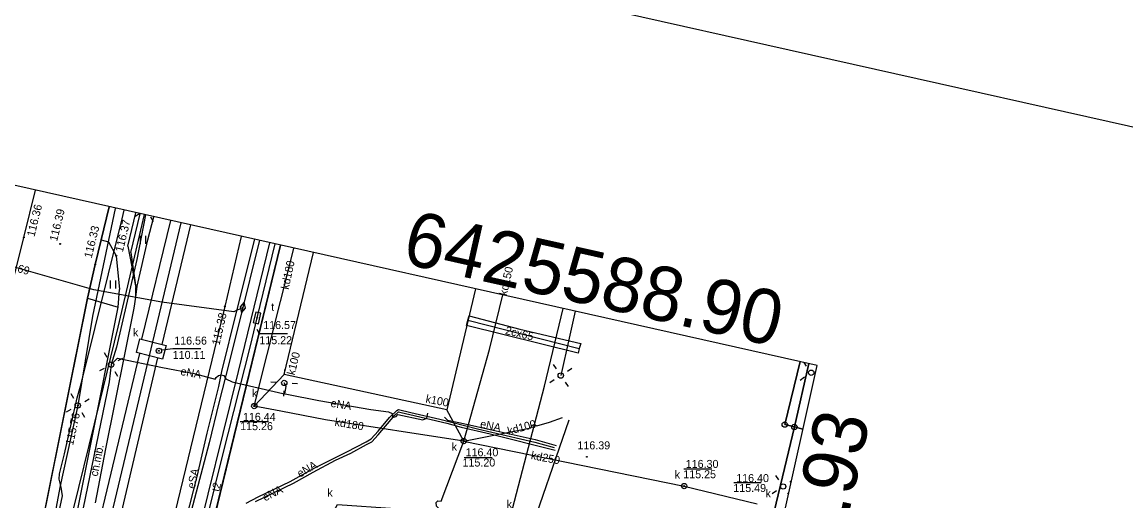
# Model space of a CAD drawing. Extents: x 6424617 to 6425697, y 5665845 to 5667190.
# Drawn here: x 6425514.4 to 6425617.8, y 5666988.2 to 5667033.1 of the extents above; entities that cross this region are included whole.
import ezdxf

# ---------------------------------------------------------------- set-up
doc = ezdxf.new("R2010")
doc.units = 0
for name, color, linetype in [('Warstwa 1', 7, 'Continuous'), ('Warstwa 10', 7, 'Continuous'), ('Warstwa 11', 7, 'Continuous'), ('Warstwa 12', 7, 'Continuous'), ('Warstwa 13', 7, 'Continuous'), ('Warstwa 14', 7, 'Continuous'), ('Warstwa 15', 7, 'Continuous'), ('Warstwa 16', 7, 'Continuous'), ('Warstwa 19', 7, 'Continuous'), ('Warstwa 2', 7, 'Continuous'), ('Warstwa 25', 7, 'Continuous'), ('Warstwa 4', 7, 'Continuous'), ('Warstwa 5', 7, 'Continuous'), ('Warstwa 6', 7, 'Continuous'), ('Warstwa 61', 7, 'Continuous'), ('Warstwa 63', 7, 'Continuous'), ('Warstwa 8', 7, 'Continuous'), ('Warstwa 9', 7, 'Continuous')]:
    doc.layers.add(name, color=color, linetype=linetype)

msp = doc.modelspace()

# ---------------------------------------------------------------- linework, layer by layer
at = {"layer": 'Warstwa 1'}
for p, q in [((6425527.3, 5666965.75), (6425538.59, 5667012.21)), ((6425527.3, 5666965.75), (6425538.59, 5667012.21)), ((6425585.85, 5666995.38), (6425587.28, 5667001.29)), ((6425585.85, 5666995.38), (6425587.28, 5667001.29)), ((6425578.8, 5666961.99), (6425586.75, 5666995.16)), ((6425578.8, 5666961.99), (6425586.75, 5666995.16)), ((6425585.85, 5666995.38), (6425586.75, 5666995.16)), ((6425585.85, 5666995.38), (6425586.75, 5666995.16)), ((6425586.75, 5666995.16), (6425587.56, 5666994.96)), ((6425586.75, 5666995.16), (6425587.56, 5666994.96))]:
    msp.add_line(p, q, dxfattribs=at)
msp.add_lwpolyline([(6425556.88, 5667008.11), (6425554.18, 5666996.75), (6425538.92, 5667000.09), (6425541.67, 5667011.52)], dxfattribs=at)
at = {"layer": 'Warstwa 10'}
for points in [[(6425536.15, 5667012.76), (6425534.48, 5667006.06), (6425533.07, 5667000.35), (6425532.79, 5666998.95), (6425531.7, 5666994.57), (6425530.74, 5666990.52), (6425529.72, 5666986.47), (6425527.95, 5666979.51), (6425526.81, 5666974.7), (6425525.74, 5666970.26), (6425525.2, 5666968.28), (6425524.22, 5666964.01), (6425522.97, 5666958.26), (6425521.24, 5666950.95), (6425520.79, 5666949.08), (6425520.74, 5666948.53), (6425520.56, 5666947.95), (6425520.42, 5666946.76), (6425520.15, 5666945.51), (6425519.52, 5666941.75), (6425519.08, 5666939.94), (6425519.11, 5666939.8), (6425519.37, 5666939.46)], [(6425536.61, 5667012.65), (6425536.33, 5667011.54), (6425535.06, 5667006.36)], [(6425535.06, 5667006.36), (6425534.21, 5667005.96), (6425527.47, 5667006.87), (6425521.11, 5667008.02), (6425511.65, 5667010.69), (6425511.04, 5667010.12), (6425510.23, 5667005.12), (6425507.8, 5666997.47), (6425502.22, 5666979.23), (6425499.7, 5666975.32), (6425496.98, 5666963.87), (6425497.18, 5666963.16), (6425549.77, 5666949.56), (6425554.77, 5666947.54), (6425572.63, 5666943.55), (6425574.23, 5666942.49)], [(6425535.06, 5667006.36), (6425533.78, 5667001.19), (6425532.8, 5666997.41), (6425531.92, 5666993.67), (6425530.22, 5666987.25), (6425528.54, 5666980.63), (6425527.03, 5666974.4), (6425525.19, 5666966.89), (6425523.24, 5666958.48), (6425521.66, 5666951.58), (6425521.06, 5666949.07), (6425521.07, 5666948.91), (6425521.13, 5666948.77), (6425521.38, 5666948.62), (6425522.52, 5666948.32), (6425524.94, 5666947.66)]]:
    msp.add_lwpolyline(points, dxfattribs=at)
for centre in [(6425585.85, 5666995.38), (6425586.75, 5666995.16)]:
    msp.add_circle(centre, 0.25, dxfattribs=at)
at = {"layer": 'Warstwa 12'}
for points in [[(6425523.1, 5667015.68), (6425523.09, 5667015.65), (6425520.96, 5667005.56), (6425519.59, 5666997.17), (6425517.95, 5666989.63), (6425516.66, 5666982.82), (6425515.78, 5666975.38), (6425516.65, 5666969.82), (6425519.41, 5666963.59), (6425522.98, 5666959.1), (6425525.11, 5666957.39)], [(6425517.24, 5666984.41), (6425518.15, 5666988.71), (6425518.04, 5666989.52), (6425517.86, 5666990.26), (6425517.89, 5666990.76), (6425518.34, 5666992.63), (6425519.54, 5666997.88), (6425519.79, 5666998.78), (6425519.94, 5666999.33), (6425523.74, 5667014.68), (6425523.94, 5667015.49)], [(6425525.8, 5667015.07), (6425523.34, 5667004.53), (6425521.64, 5666997.49), (6425518.65, 5666985.42), (6425517.46, 5666980.78), (6425518.28, 5666980.1), (6425521.66, 5666979.15), (6425522.02, 5666979.46), (6425522.25, 5666979.42), (6425522.45, 5666979.11), (6425522.64, 5666978.87), (6425523.11, 5666978.77)], [(6425525.95, 5667015.04), (6425525.14, 5667010.87), (6425523.21, 5667002.64), (6425522.71, 5667001.01), (6425522.52, 5666999.4), (6425520.09, 5666987.57)], [(6425525.61, 5667003.38), (6425528.31, 5667014.51)], [(6425530.17, 5667014.1), (6425527.48, 5667002.9)], [(6425534.91, 5667013.03), (6425533.36, 5667006.46), (6425526.73, 5666978.99), (6425525.91, 5666975.56)], [(6425526.97, 5666967.96), (6425527.09, 5666969.33), (6425530.39, 5666983.06), (6425534.64, 5667000.36), (6425537.6, 5667012.43)], [(6425526.97, 5666967.96), (6425527.47, 5666969.27), (6425527.47, 5666969.48), (6425528.74, 5666974.59), (6425533.17, 5666992.41), (6425535.79, 5667002.78), (6425536.4, 5667005.39), (6425538.09, 5667012.32)], [(6425555.76, 5666993.84), (6425542.8, 5666995.83), (6425538.63, 5666996.64), (6425536.13, 5666997.12), (6425539.8, 5667011.77), (6425539.84, 5667011.93)], [(6425555.76, 5666993.84), (6425558.18, 5667002.42), (6425559.42, 5667007.54)], [(6425539.12, 5666967.53), (6425537.76, 5666968.09), (6425533.53, 5666969.08), (6425543.92, 5666987.9), (6425560.14, 5666986.76), (6425563.34, 5666998.97), (6425565.07, 5667006.27)], [(6425566.21, 5667006.01), (6425565.63, 5667003.5), (6425564.86, 5666999.98)], [(6425556.14, 5667005.16), (6425566.59, 5667002.52)], [(6425512.92, 5666950.08), (6425516.34, 5666964.17), (6425518.58, 5666973.48), (6425525.42, 5667002.06)], [(6425527.07, 5667001.64), (6425520.14, 5666972.04), (6425517.93, 5666962.8), (6425514.66, 5666949.63)], [(6425522.71, 5667001.01), (6425523.3, 5667001.62), (6425527.52, 5667000.75), (6425530.5, 5667000.17), (6425532.47, 5666999.64), (6425532.55, 5666999.8), (6425532.78, 5666999.99), (6425533.02, 5667000.06), (6425533.29, 5666999.98), (6425533.48, 5666999.67), (6425534.05, 5666999.39), (6425538.81, 5666998.29), (6425539, 5666998.27), (6425539.2, 5666998.24), (6425542.17, 5666997.63), (6425547.05, 5666996.79), (6425548.71, 5666996.58), (6425549.06, 5666996.42), (6425549.09, 5666996.11), (6425549.21, 5666996.07), (6425549.44, 5666996.14), (6425549.6, 5666996.33), (6425551.92, 5666995.84), (6425552.31, 5666995.99), (6425552.39, 5666996.46)], [(6425536.13, 5666997.12), (6425538.92, 5667000.09)], [(6425539, 5666998.27), (6425539.12, 5666998.94), (6425538.94, 5666999.29)], [(6425535.38, 5666988), (6425536.51, 5666988.62), (6425539.5, 5666990.03), (6425541.81, 5666991.33), (6425544.07, 5666992.45), (6425544.82, 5666992.83), (6425546.61, 5666993.76), (6425547.09, 5666994.06), (6425547.74, 5666994.76), (6425548.81, 5666996.04), (6425549.49, 5666996.71), (6425549.66, 5666996.81), (6425550.81, 5666996.53), (6425553.53, 5666995.89), (6425557.06, 5666994.99), (6425562.44, 5666993.74), (6425564.25, 5666993.23)], [(6425536.25, 5666988.17), (6425539.82, 5666989.9), (6425541.66, 5666990.93), (6425543.74, 5666992.04), (6425545.17, 5666992.71), (6425546.64, 5666993.52), (6425547.16, 5666993.78), (6425547.75, 5666994.41), (6425549.32, 5666996.28), (6425549.65, 5666996.59), (6425549.91, 5666996.51), (6425550.72, 5666996.33), (6425554.19, 5666995.53), (6425555.53, 5666995.13), (6425558.25, 5666994.53), (6425564.33, 5666992.98)], [(6425553.97, 5666996.08), (6425554.25, 5666995.8), (6425555.46, 5666995.55), (6425558.81, 5666994.79), (6425562.46, 5666993.99), (6425564.44, 5666993.41)], [(6425555.76, 5666993.84), (6425554.18, 5666996.75)], [(6425555.76, 5666993.84), (6425562.05, 5666995.09), (6425562.21, 5666995.32), (6425562.38, 5666995.39), (6425562.61, 5666995.26), (6425563.81, 5666995.61), (6425565.01, 5666996.05)], [(6425558.04, 5666973.86), (6425561.36, 5666983.42), (6425564.44, 5666992.3), (6425565.64, 5666995.83)], [(6425539.12, 5666967.53), (6425539.77, 5666967.96), (6425540.47, 5666968.42), (6425545.97, 5666971.52), (6425546.88, 5666973.41), (6425553.39, 5666987.53), (6425553.21, 5666987.74), (6425553.19, 5666988.09), (6425553.35, 5666988.22), (6425553.65, 5666988.21), (6425555.76, 5666993.84)], [(6425555.75, 5666993.84), (6425576.42, 5666989.62), (6425583.27, 5666987.96)]]:
    msp.add_lwpolyline(points, dxfattribs=at)
at = {"layer": 'Warstwa 14'}
for p, q in [((6425537.46, 5666995.63), (6425534.81, 5666995.63)), ((6425558.42, 5666992.28), (6425555.81, 5666992.28)), ((6425579.03, 5666991.19), (6425576.4, 5666991.19)), ((6425583.64, 5666989.92), (6425581.08, 5666989.92))]:
    msp.add_line(p, q, dxfattribs=at)
for points in [[(6425539.26, 5667003.88), (6425536.61, 5667003.88), (6425536.39, 5667004.31)], [(6425531.13, 5667002.5), (6425528.5, 5667002.5), (6425527.51, 5667002.35)]]:
    msp.add_lwpolyline(points, dxfattribs=at)
for centre in [(6425533.36, 5667006.46), (6425536.4, 5667005.39), (6425527.2, 5667002.3), (6425519.59, 5666997.17), (6425536.13, 5666997.12), (6425555.76, 5666993.84), (6425576.42, 5666989.62)]:
    msp.add_circle(centre, 0.045, dxfattribs=at)
at = {"layer": 'Warstwa 16'}
msp.add_lwpolyline([(6425525.42, 5667003.43), (6425527.86, 5667002.81), (6425527.54, 5667001.52), (6425525.09, 5667002.15)], close=True, dxfattribs=at)
at = {"layer": 'Warstwa 19'}
msp.add_lwpolyline([(6425534.94, 5667005.87), (6425535.3, 5667006.3), (6425535.18, 5667006.85), (6425534.82, 5667006.42)], close=True, dxfattribs=at)
at = {"layer": 'Warstwa 2'}
for points in [[(6425524.57, 5667011.52), (6425525.45, 5667015.15)], [(6425588.12, 5667001.1), (6425586.75, 5666995.16), (6425587.56, 5666994.96)]]:
    msp.add_lwpolyline(points, dxfattribs=at)
for centre in [(6425522.71, 5667001.01), (6425564.86, 5666999.98), (6425588.33, 5667000.25), (6425538.94, 5666999.29), (6425519.59, 5666997.17), (6425585.7, 5666989.58)]:
    msp.add_circle(centre, 0.25, dxfattribs=at)
at = {"layer": 'Warstwa 25'}
for centre in [(6425514.53, 5667012.93), (6425517.93, 5667012.32), (6425521.21, 5667010.39), (6425523.2, 5667011.22), (6425567.3, 5666992.36)]:
    msp.add_circle(centre, 0.045, dxfattribs=at)
at = {"layer": 'Warstwa 4'}
for points in [[(6425525.39, 5667015.14), (6425524.96, 5667014.89)], [(6425526.41, 5667014.86), (6425526.66, 5667014.42)], [(6425522.35, 5667001.67), (6425522.11, 5667002.11)], [(6425523.37, 5667001.38), (6425523.81, 5667001.62)], [(6425587.9, 5667000.86), (6425587.66, 5667001.21)], [(6425522.06, 5667000.65), (6425521.62, 5667000.41)], [(6425523.07, 5667000.36), (6425523.31, 5666999.92)], [(6425538.98, 5667000.04), (6425539.01, 5667000.54)], [(6425564.45, 5667000.61), (6425564.17, 5667001.03)], [(6425565.49, 5667000.4), (6425565.91, 5667000.67)], [(6425538.19, 5666999.34), (6425537.69, 5666999.36)], [(6425539.69, 5666999.25), (6425540.19, 5666999.23)], [(6425564.24, 5666999.57), (6425563.82, 5666999.29)], [(6425565.28, 5666999.36), (6425565.55, 5666998.94)], [(6425587.71, 5666999.82), (6425587.3, 5666999.53)], [(6425519.21, 5666997.82), (6425518.96, 5666998.25)], [(6425538.9, 5666998.55), (6425538.87, 5666998.05)], [(6425520.24, 5666997.55), (6425520.67, 5666997.8)], [(6425518.94, 5666996.79), (6425518.51, 5666996.54)], [(6425519.97, 5666996.52), (6425520.22, 5666996.09)], [(6425585.28, 5666990.2), (6425585, 5666990.62)], [(6425586.32, 5666990), (6425586.47, 5666990.1)], [(6425585.08, 5666989.16), (6425584.66, 5666988.88)], [(6425586.12, 5666988.96), (6425586.19, 5666988.85)]]:
    msp.add_lwpolyline(points, dxfattribs=at)
msp.add_lwpolyline([(6425536.27, 5667005.93), (6425536.04, 5667004.95), (6425536.53, 5667004.84), (6425536.76, 5667005.82)], close=True, dxfattribs=at)
for centre in [(6425527.2, 5667002.3), (6425536.13, 5666997.12), (6425555.76, 5666993.84), (6425576.42, 5666989.62)]:
    msp.add_circle(centre, 0.25, dxfattribs=at)
at = {"layer": 'Warstwa 5'}
for p, q in [((6425524.57, 5667011.52), (6425525.45, 5667015.15)), ((6425526.17, 5667012.69), (6425526.71, 5667014.87)), ((6425521.21, 5667010.39), (6425521.78, 5667012.72)), ((6425521.78, 5667012.72), (6425522.47, 5667012.53)), ((6425522.47, 5667012.53), (6425523.2, 5667011.22)), ((6425525.16, 5667008.35), (6425526.17, 5667012.69)), ((6425525.46, 5667012.33), (6425525.46, 5667013.08)), ((6425525.96, 5667012.33), (6425525.96, 5667013.08)), ((6425524.57, 5667011.52), (6425525.03, 5667008.24)), ((6425520.49, 5667007.25), (6425521.21, 5667010.39)), ((6425523.2, 5667011.22), (6425523.5, 5667008.06)), ((6425522.66, 5667008.15), (6425522.66, 5667008.9)), ((6425523.16, 5667008.15), (6425523.16, 5667008.9)), ((6425525.02, 5667007.32), (6425525.16, 5667008.35)), ((6425523.37, 5667006.39), (6425523.5, 5667008.06)), ((6425525.02, 5667007.32), (6425525.03, 5667008.24)), ((6425520.49, 5667007.25), (6425523.37, 5667006.39))]:
    msp.add_line(p, q, dxfattribs=at)
at = {"layer": 'Warstwa 6'}
for points in [[(6425511.35, 5667018.31), (6425496.12, 5666954.85), (6425522.25, 5666945.04), (6425525.2, 5666957.05), (6425527.3, 5666965.75), (6425538.59, 5667012.21)], [(6425522.53, 5667015.81), (6425521.78, 5667012.72), (6425521.21, 5667010.39), (6425520.49, 5667007.25), (6425515.29, 5666981.32)], [(6425513.34, 5667008.15), (6425514.53, 5667012.93)], [(6425538.59, 5667012.21), (6425527.3, 5666965.75), (6425576.81, 5666953.74), (6425578.8, 5666961.99), (6425586.75, 5666995.16), (6425585.85, 5666995.38), (6425587.28, 5667001.29)], [(6425587.28, 5667001.29), (6425585.85, 5666995.38), (6425586.75, 5666995.16), (6425587.56, 5666994.96)], [(6425587.56, 5666994.96), (6425586.75, 5666995.16), (6425578.8, 5666961.99), (6425580.1, 5666961.67)]]:
    msp.add_lwpolyline(points, dxfattribs=at)
at = {"layer": 'Warstwa 61'}
msp.add_lwpolyline([(6425481.04, 5666812.6), (6425491.4, 5666857.13), (6425513.74, 5666949.13), (6425526.48, 5667002.48), (6425529.29, 5667014.29)], dxfattribs=at)
at = {"layer": 'Warstwa 63'}
for points in [[(6424616.75, 5666029.38), (6424876.88, 5667189.58), (6425697.3, 5667005.64), (6425437.18, 5665845.44)], [(6425341.16, 5665895.98), (6425588.9, 5667000.93), (6424898.31, 5667155.76), (6424650.57, 5666050.81)]]:
    msp.add_lwpolyline(points, close=True, dxfattribs=at)
at = {"layer": 'Warstwa 8'}
for p, q in [((6425514.53, 5667012.93), (6425515.62, 5667017.36)), ((6425521.78, 5667012.72), (6425522.53, 5667015.81)), ((6425513.34, 5667008.15), (6425514.53, 5667012.93)), ((6425521.21, 5667010.39), (6425521.78, 5667012.72)), ((6425520.49, 5667007.25), (6425521.21, 5667010.39)), ((6425515.29, 5666981.32), (6425520.49, 5667007.25)), ((6425586.75, 5666995.16), (6425588.12, 5667001.1)), ((6425586.75, 5666995.16), (6425587.56, 5666994.96))]:
    msp.add_line(p, q, dxfattribs=at)
msp.add_lwpolyline([(6425556.28, 5667005.59), (6425561.03, 5667004.34), (6425566.73, 5667002.98), (6425566.59, 5667002.52), (6425566.5, 5667002.09), (6425556.03, 5667004.67), (6425556.14, 5667005.16)], close=True, dxfattribs=at)
at = {"layer": 'Warstwa 9'}
for p, q in [((6425521.78, 5667012.72), (6425522.53, 5667015.81)), ((6425524.28, 5667012.12), (6425525.04, 5667015.25)), ((6425521.78, 5667012.72), (6425522.47, 5667012.53)), ((6425522.47, 5667012.53), (6425523.2, 5667011.22)), ((6425524.28, 5667012.12), (6425525.03, 5667008.24)), ((6425523.2, 5667011.22), (6425523.5, 5667008.06)), ((6425523.37, 5667006.39), (6425523.5, 5667008.06)), ((6425524.88, 5667006.29), (6425525.02, 5667007.32)), ((6425525.02, 5667007.32), (6425525.03, 5667008.24)), ((6425520.77, 5666993.4), (6425523.37, 5667006.39)), ((6425522.23, 5666993.1), (6425524.88, 5667006.29)), ((6425518.42, 5666981.6), (6425520.77, 5666993.4)), ((6425521.24, 5666988.06), (6425522.23, 5666993.1))]:
    msp.add_line(p, q, dxfattribs=at)

# ---------------------------------------------------------------- texts
at = {"layer": 'Warstwa 11'}
msp.add_text('eSA', height=0.75, rotation=77.3264, dxfattribs=at).set_placement((6425530.55, 5666989.32))
at = {"layer": 'Warstwa 13'}
for s, rotation, p in [('kd180', 77.9051, (6425539.35, 5667008)), ('kd150', 77.0857, (6425559.79, 5667007.42)), ('2cx65', 346.5421, (6425559.61, 5667003.88)), ('k100', 75.9742, (6425539.91, 5666999.97)), ('eNA', 349.6876, (6425529.17, 5667000.04)), ('k100', 349.1891, (6425552.15, 5666997.46)), ('eNA', 350.971, (6425543.25, 5666997.05)), ('kd180', 350.6444, (6425543.63, 5666995.28)), ('eNA', 347.9286, (6425557.25, 5666995.12)), ('kd100', 15.5959, (6425559.98, 5666994.4)), ('kd250', 349.1376, (6425562.02, 5666992.16)), ('eNA', 30.3037, (6425540.42, 5666990.4)), ('t2', 76.7248, (6425532.85, 5666989.04)), ('eNA', 26.5451, (6425537.14, 5666988.17))]:
    msp.add_text(s, height=0.75, rotation=rotation, dxfattribs=at).set_placement(p)
at = {"layer": 'Warstwa 14'}
for s, rotation, p in [('114.69', 344.2388, (6425512, 5667010.23)), ('115.38', 77.1201, (6425532.87, 5667002.78)), ('115.76', 77.7275, (6425519.15, 5666993.4))]:
    msp.add_text(s, height=0.75, rotation=rotation, dxfattribs=at).set_placement(p)
for s, p in [('115.22', (6425536.61, 5667002.92)), ('110.11', (6425528.49, 5667001.54)), ('115.26', (6425534.81, 5666994.86)), ('115.20', (6425555.65, 5666991.45)), ('115.25', (6425576.34, 5666990.35)), ('115.49', (6425581.03, 5666989.06))]:
    msp.add_text(s, height=0.75, dxfattribs=at).set_placement(p)
at = {"layer": 'Warstwa 15'}
for s, p in [('116.57', (6425536.97, 5667004.34)), ('116.56', (6425528.63, 5667002.88)), ('116.44', (6425535.07, 5666995.73)), ('116.40', (6425555.94, 5666992.41)), ('116.30', (6425576.57, 5666991.32)), ('116.40', (6425581.3, 5666989.99))]:
    msp.add_text(s, height=0.75, dxfattribs=at).set_placement(p)
at = {"layer": 'Warstwa 25'}
for s, rotation, p in [('116.36', 76.1977, (6425515.53, 5667012.95)), ('116.39', 76.1977, (6425517.65, 5667012.52)), ('116.37', 76.4039, (6425523.81, 5667011.5)), ('116.33', 76.255, (6425520.89, 5667010.94))]:
    msp.add_text(s, height=0.75, rotation=rotation, dxfattribs=at).set_placement(p)
msp.add_text('116.39', height=0.75, dxfattribs=at).set_placement((6425566.42, 5666993.06))
at = {"layer": 'Warstwa 5'}
for s, p in [('t', (6425537.72, 5667006.04)), ('k', (6425524.77, 5667003.65)), ('k', (6425535.92, 5666997.96)), ('k', (6425554.64, 5666992.93)), ('k', (6425575.54, 5666990.32)), ('k', (6425542.98, 5666988.63)), ('k', (6425584.05, 5666988.56)), ('k', (6425559.79, 5666987.55))]:
    msp.add_text(s, height=0.75, dxfattribs=at).set_placement(p)
at = {"layer": 'Warstwa 63'}
for s, rotation, p in [('6425588.90', 347.3629, (6425549.85, 5667010.55)), ('5667000.93', 77.3629, (6425586, 5666960.83))]:
    msp.add_text(s, height=5.096, rotation=rotation, dxfattribs=at).set_placement(p)
at = {"layer": 'Warstwa 9'}
msp.add_text('ch.mb.', height=0.75, rotation=78.8848, dxfattribs=at).set_placement((6425521.45, 5666990.48))

doc.saveas('drawing.dxf')
